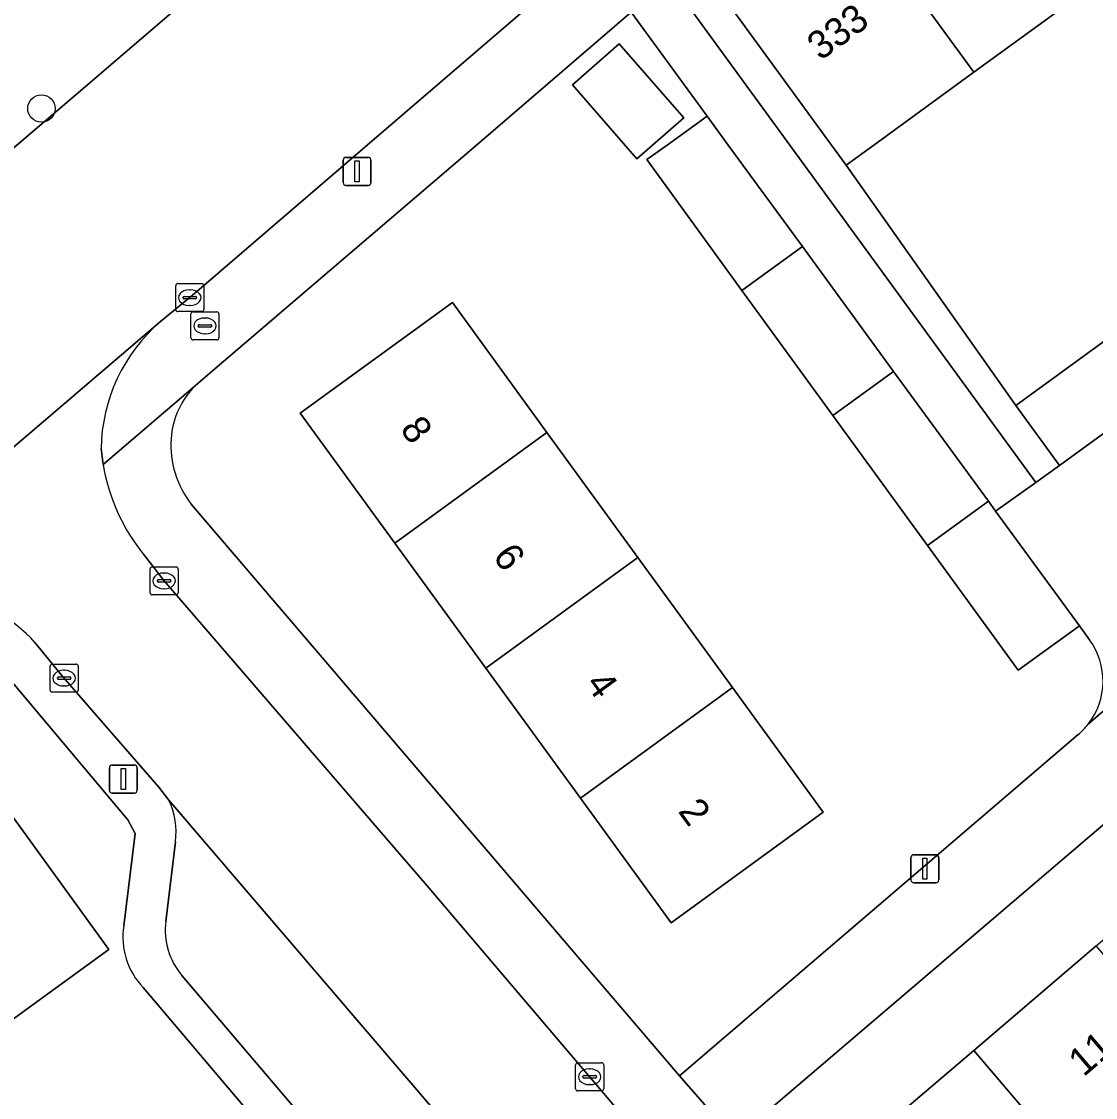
# Model space of a CAD drawing. Extents: x 159039 to 160102, y 381214 to 382524.
# Drawn here: x 159296.1 to 159334.39, y 381466.04 to 381504.4 of the extents above; entities that cross this region are included whole.
import ezdxf

# ---------------------------------------------------------------- set-up
doc = ezdxf.new("R2010")
doc.units = 0
for name, color, linetype in [('IMGEO_Boom', 7, 'Continuous'), ('IMGEO_Brandkraan', 7, 'Continuous'), ('IMGEO_Erf', 7, 'Continuous'), ('IMGEO_Groenvoorziening', 7, 'Continuous'), ('IMGEO_Kolk', 7, 'Continuous'), ('IMGEO_Lichtmast', 7, 'Continuous'), ('IMGEO_Pand', 7, 'Continuous'), ('IMGEO_Pand_nummerreeks', 7, 'Continuous'), ('IMGEO_Parkeervlak_open', 7, 'Continuous'), ('IMGEO_Rijbaan_lokaal_gesloten', 7, 'Continuous'), ('IMGEO_Rijbaan_lokaal_open', 7, 'Continuous'), ('IMGEO_Voetpad_open', 7, 'Continuous')]:
    doc.layers.add(name, color=color, linetype=linetype)

msp = doc.modelspace()

# ---------------------------------------------------------------- linework, layer by layer
at = {"layer": 'IMGEO_Boom'}
msp.add_circle((159296.812, 381501.302), 0.489, dxfattribs=at)
at = {"layer": 'IMGEO_Brandkraan'}
for p, q in [((159302.142, 381493.125), (159302.142, 381493.977)), ((159302.217, 381494.051), (159303.069, 381494.051)), ((159302.63, 381493.831), (159302.655, 381493.831)), ((159303.143, 381493.977), (159303.143, 381493.125)), ((159302.401, 381493.545), (159302.401, 381493.557)), ((159302.839, 381493.508), (159302.441, 381493.508)), ((159302.444, 381493.594), (159302.842, 381493.594)), ((159302.885, 381493.557), (159302.885, 381493.545)), ((159303.069, 381493.051), (159302.217, 381493.051)), ((159302.653, 381493.271), (159302.628, 381493.271))]:
    msp.add_line(p, q, dxfattribs=at)
for points in [[(159302.142, 381493.125), (159302.142, 381493.977)], [(159302.217, 381494.051), (159303.069, 381494.051)], [(159303.143, 381493.977), (159303.143, 381493.125)], [(159303.069, 381493.051), (159302.217, 381493.051)]]:
    msp.add_lwpolyline(points, dxfattribs=at)
for centre, radius, start, end in [((159302.219, 381493.975), 0.0765, 91.552, 178.448), ((159302.219, 381493.975), 0.0765, 91.552, 178.448), ((159303.067, 381493.975), 0.0765, 1.552, 88.448), ((159303.067, 381493.975), 0.0765, 1.552, 88.448), ((159302.441, 381493.554), 0.0403, 85.8775, 175.7526), ((159302.438, 381493.544), 0.0366, 178.938, 274.7102), ((159302.842, 381493.551), 0.043, 264.8664, 352.4533), ((159302.846, 381493.556), 0.0386, 1.7309, 96.639), ((159302.219, 381493.127), 0.0765, 181.552, 268.448), ((159302.219, 381493.127), 0.0765, 181.552, 268.448), ((159303.067, 381493.127), 0.0765, 271.552, 358.448), ((159303.067, 381493.127), 0.0765, 271.552, 358.448)]:
    msp.add_arc(centre, radius, start, end, dxfattribs=at)
for centre, major_axis, ratio, start_param, end_param in [((159302.629, 381493.551), (-0.387, 0.002), 0.722429, 4.712389, 7.853982), ((159302.654, 381493.551), (-0.39, 0.002), 0.717154, 1.570796, 4.712389)]:
    msp.add_ellipse(centre, major_axis=major_axis, ratio=ratio, start_param=start_param, end_param=end_param, dxfattribs=at)
at = {"layer": 'IMGEO_Erf'}
for points in [[(159334.646, 381505.941), (159330.052, 381502.597), (159326.485, 381500), (159325.501, 381499.284), (159331.551, 381490.716), (159334.784, 381493.064), (159336.342, 381490.923), (159337.788, 381491.975), (159339.116, 381492.941), (159337.559, 381495.079), (159340.829, 381497.453), (159344.336, 381500), (159345.362, 381500.745), (159349.862, 381504.013), (159353.089, 381506.357)], [(159325.031, 381490.357), (159321.789, 381494.812), (159318.393, 381499.48), (159319.118, 381500), (159320.55, 381501.028), (159317.844, 381504.732), (159312.319, 381500), (159302.583, 381491.662), (159302.308, 381491.427)], [(159334.18, 381482.359), (159333.817, 381482.856), (159331.64, 381481.272), (159328.405, 381485.718), (159325.031, 381490.357)], [(159302.152, 381487.194), (159319.563, 381466.81), (159333.778, 381478.977)], [(159299.748, 381472.159), (159300.152, 381475.447), (159299.893, 381475.941), (159295.018, 381481.729)], [(159295.252, 381476.781), (159299.214, 381471.315), (159294.541, 381467.929)], [(159294.53, 381454.94), (159296.091, 381452.788), (159297.79, 381454.02), (159298.801, 381454.752), (159297.24, 381456.904), (159300.71, 381459.419), (159305.261, 381462.717), (159306.821, 381460.565), (159307.749, 381461.325), (159300.446, 381469.957)]]:
    msp.add_lwpolyline(points, dxfattribs=at)
for points in [[(159318.045, 381499.513), (159315.742, 381502.147), (159317.415, 381503.609), (159319.718, 381500.975)], [(159318.076, 381485.295), (159321.45, 381480.657), (159324.688, 381476.207), (159319.264, 381472.261), (159316.027, 381476.711), (159312.653, 381481.348), (159309.41, 381485.806), (159306.042, 381490.435), (159311.466, 381494.381), (159314.834, 381489.752)], [(159353.568, 381466.332), (159356.93, 381469.203), (159358.656, 381467.182), (159359.612, 381467.998), (159357.886, 381470.019), (159362.143, 381473.653), (159366.296, 381477.198), (159368.022, 381475.177), (159369.913, 381476.791), (159364.087, 381483.617), (159355.565, 381493.598), (159321.537, 381464.546), (159335.677, 381447.899), (159337.911, 381449.806), (159336.35, 381451.634), (159340.649, 381455.304), (159344.05, 381458.207), (159345.776, 381456.186), (159346.746, 381457.014), (159345.02, 381459.035), (159349.355, 381462.736), (159351.081, 381460.715), (159352.008, 381461.507), (159350.282, 381463.528)], [(159347.282, 381473.694), (159343.069, 381470.098), (159338.734, 381466.397), (159334.362, 381462.665), (159330.206, 381459.117), (159325.893, 381464.168), (159330.049, 381467.715), (159334.421, 381471.448), (159338.756, 381475.149), (159342.969, 381478.745), (159347.286, 381482.43), (159351.543, 381486.064), (159355.841, 381489.733), (159360.153, 381484.682), (159355.856, 381481.014), (159351.599, 381477.38)]]:
    msp.add_lwpolyline(points, close=True, dxfattribs=at)
for centre, radius, start, end in [((159304.324, 381489.355), 2.891, 134.2059, 176.5428), ((159304.84, 381489.293), 3.411, 176.0271, 217.9783), ((159332.16, 381480.884), 2.501, 322.1067, 36.1428), ((159332.232, 381480.817), 2.403, 310.04, 322.324), ((159302.279, 381471.75), 2.564, 170.8183, 224.3573)]:
    msp.add_arc(centre, radius, start, end, dxfattribs=at)
at = {"layer": 'IMGEO_Groenvoorziening'}
msp.add_lwpolyline([(159325.501, 381499.284), (159324.981, 381500), (159321.492, 381504.791), (159320.117, 381506.679), (159319.202, 381505.896), (159332.26, 381487.965), (159333.111, 381488.573), (159331.551, 381490.716)], close=True, dxfattribs=at)
at = {"layer": 'IMGEO_Kolk'}
for p, q in [((159301.601, 381494.133), (159301.601, 381494.985)), ((159301.676, 381495.059), (159302.528, 381495.059)), ((159302.602, 381494.985), (159302.602, 381494.133)), ((159301.86, 381494.553), (159301.86, 381494.565)), ((159302.298, 381494.516), (159301.9, 381494.516)), ((159301.903, 381494.602), (159302.301, 381494.602)), ((159302.089, 381494.839), (159302.114, 381494.839)), ((159302.344, 381494.565), (159302.344, 381494.553)), ((159302.112, 381494.279), (159302.087, 381494.279)), ((159302.528, 381494.059), (159301.676, 381494.059)), ((159300.686, 381484.033), (159300.686, 381484.885)), ((159300.761, 381484.959), (159301.613, 381484.959)), ((159301.687, 381484.885), (159301.687, 381484.033)), ((159300.988, 381484.502), (159301.386, 381484.502)), ((159301.174, 381484.739), (159301.199, 381484.739)), ((159300.945, 381484.453), (159300.945, 381484.465)), ((159301.383, 381484.416), (159300.985, 381484.416)), ((159301.197, 381484.179), (159301.172, 381484.179)), ((159301.429, 381484.465), (159301.429, 381484.453)), ((159301.613, 381483.959), (159300.761, 381483.959)), ((159297.197, 381481.49), (159298.049, 381481.49)), ((159297.122, 381480.564), (159297.122, 381481.416)), ((159297.61, 381481.27), (159297.635, 381481.27)), ((159298.123, 381481.416), (159298.123, 381480.564)), ((159297.381, 381480.984), (159297.381, 381480.996)), ((159297.819, 381480.947), (159297.421, 381480.947)), ((159297.424, 381481.033), (159297.822, 381481.033)), ((159297.633, 381480.71), (159297.608, 381480.71)), ((159297.865, 381480.996), (159297.865, 381480.984)), ((159298.049, 381480.49), (159297.197, 381480.49)), ((159315.933, 381467.274), (159316.785, 381467.274)), ((159315.858, 381466.348), (159315.858, 381467.2)), ((159316.346, 381467.054), (159316.371, 381467.054)), ((159316.859, 381467.2), (159316.859, 381466.348)), ((159316.117, 381466.768), (159316.117, 381466.78)), ((159316.555, 381466.731), (159316.157, 381466.731)), ((159316.16, 381466.817), (159316.558, 381466.817)), ((159316.369, 381466.494), (159316.344, 381466.494)), ((159316.601, 381466.78), (159316.601, 381466.768)), ((159316.785, 381466.274), (159315.933, 381466.274))]:
    msp.add_line(p, q, dxfattribs=at)
for points in [[(159301.601, 381494.133), (159301.601, 381494.985)], [(159301.676, 381495.059), (159302.528, 381495.059)], [(159302.602, 381494.985), (159302.602, 381494.133)], [(159302.528, 381494.059), (159301.676, 381494.059)], [(159300.686, 381484.033), (159300.686, 381484.885)], [(159300.761, 381484.959), (159301.613, 381484.959)], [(159301.687, 381484.885), (159301.687, 381484.033)], [(159301.613, 381483.959), (159300.761, 381483.959)], [(159297.197, 381481.49), (159298.049, 381481.49)], [(159297.122, 381480.564), (159297.122, 381481.416)], [(159298.123, 381481.416), (159298.123, 381480.564)], [(159298.049, 381480.49), (159297.197, 381480.49)], [(159315.933, 381467.274), (159316.785, 381467.274)], [(159315.858, 381466.348), (159315.858, 381467.2)], [(159316.859, 381467.2), (159316.859, 381466.348)], [(159316.785, 381466.274), (159315.933, 381466.274)]]:
    msp.add_lwpolyline(points, dxfattribs=at)
for centre, radius, start, end in [((159301.678, 381494.983), 0.0765, 91.552, 178.448), ((159301.678, 381494.983), 0.0765, 91.552, 178.448), ((159302.526, 381494.983), 0.0765, 1.552, 88.448), ((159302.526, 381494.983), 0.0765, 1.552, 88.448), ((159301.9, 381494.562), 0.0403, 85.8775, 175.7526), ((159301.897, 381494.552), 0.0366, 178.938, 274.7102), ((159302.301, 381494.559), 0.043, 264.8664, 352.4533), ((159302.305, 381494.564), 0.0386, 1.7309, 96.639), ((159301.678, 381494.135), 0.0765, 181.552, 268.448), ((159301.678, 381494.135), 0.0765, 181.552, 268.448), ((159302.526, 381494.135), 0.0765, 271.552, 358.448), ((159302.526, 381494.135), 0.0765, 271.552, 358.448), ((159300.763, 381484.883), 0.0765, 91.552, 178.448), ((159300.763, 381484.883), 0.0765, 91.552, 178.448), ((159301.611, 381484.883), 0.0765, 1.552, 88.448), ((159301.611, 381484.883), 0.0765, 1.552, 88.448), ((159300.985, 381484.462), 0.0403, 85.8775, 175.7526), ((159301.39, 381484.464), 0.0386, 1.7309, 96.639), ((159300.982, 381484.452), 0.0366, 178.938, 274.7102), ((159301.386, 381484.459), 0.043, 264.8664, 352.4533), ((159300.763, 381484.035), 0.0765, 181.552, 268.448), ((159300.763, 381484.035), 0.0765, 181.552, 268.448), ((159301.611, 381484.035), 0.0765, 271.552, 358.448), ((159301.611, 381484.035), 0.0765, 271.552, 358.448), ((159297.199, 381481.414), 0.0765, 91.552, 178.448), ((159297.199, 381481.414), 0.0765, 91.552, 178.448), ((159298.047, 381481.414), 0.0765, 1.552, 88.448), ((159298.047, 381481.414), 0.0765, 1.552, 88.448), ((159297.421, 381480.993), 0.0403, 85.8775, 175.7526), ((159297.418, 381480.983), 0.0366, 178.938, 274.7102), ((159297.822, 381480.99), 0.043, 264.8664, 352.4533), ((159297.826, 381480.995), 0.0386, 1.7309, 96.639), ((159297.199, 381480.566), 0.0765, 181.552, 268.448), ((159297.199, 381480.566), 0.0765, 181.552, 268.448), ((159298.047, 381480.566), 0.0765, 271.552, 358.448), ((159298.047, 381480.566), 0.0765, 271.552, 358.448), ((159315.935, 381467.198), 0.0765, 91.552, 178.448), ((159315.935, 381467.198), 0.0765, 91.552, 178.448), ((159316.783, 381467.198), 0.0765, 1.552, 88.448), ((159316.783, 381467.198), 0.0765, 1.552, 88.448), ((159316.157, 381466.777), 0.0403, 85.8775, 175.7526), ((159316.154, 381466.767), 0.0366, 178.938, 274.7102), ((159316.558, 381466.774), 0.043, 264.8664, 352.4533), ((159316.562, 381466.779), 0.0386, 1.7309, 96.639), ((159315.935, 381466.35), 0.0765, 181.552, 268.448), ((159315.935, 381466.35), 0.0765, 181.552, 268.448), ((159316.783, 381466.35), 0.0765, 271.552, 358.448), ((159316.783, 381466.35), 0.0765, 271.552, 358.448)]:
    msp.add_arc(centre, radius, start, end, dxfattribs=at)
for centre, major_axis, ratio, start_param, end_param in [((159302.088, 381494.559), (-0.387, 0.002), 0.722429, 4.712389, 7.853982), ((159302.113, 381494.559), (-0.39, 0.002), 0.717154, 1.570796, 4.712389), ((159301.173, 381484.459), (-0.387, 0.002), 0.722429, 4.712389, 7.853982), ((159301.198, 381484.459), (-0.39, 0.002), 0.717154, 1.570796, 4.712389), ((159297.609, 381480.99), (-0.387, 0.002), 0.722429, 4.712389, 7.853982), ((159297.634, 381480.99), (-0.39, 0.002), 0.717154, 1.570796, 4.712389), ((159316.345, 381466.774), (-0.387, 0.002), 0.722429, 4.712389, 7.853982), ((159316.37, 381466.774), (-0.39, 0.002), 0.717154, 1.570796, 4.712389)]:
    msp.add_ellipse(centre, major_axis=major_axis, ratio=ratio, start_param=start_param, end_param=end_param, dxfattribs=at)
at = {"layer": 'IMGEO_Lichtmast'}
for p, q in [((159307.57, 381498.661), (159307.57, 381499.461)), ((159307.57, 381499.461), (159307.57, 381498.661)), ((159307.67, 381499.561), (159308.46, 381499.561)), ((159308.46, 381499.561), (159307.67, 381499.561)), ((159308.56, 381499.461), (159308.56, 381498.661)), ((159308.56, 381498.661), (159308.56, 381499.461)), ((159308.46, 381498.561), (159307.67, 381498.561)), ((159307.67, 381498.561), (159308.46, 381498.561)), ((159299.236, 381476.991), (159299.236, 381477.791)), ((159299.236, 381477.791), (159299.236, 381476.991)), ((159299.336, 381477.891), (159300.126, 381477.891)), ((159300.126, 381477.891), (159299.336, 381477.891)), ((159300.226, 381477.791), (159300.226, 381476.991)), ((159300.226, 381476.991), (159300.226, 381477.791)), ((159300.126, 381476.891), (159299.336, 381476.891)), ((159299.336, 381476.891), (159300.126, 381476.891)), ((159327.811, 381473.794), (159327.811, 381474.594)), ((159327.811, 381474.594), (159327.811, 381473.794)), ((159327.911, 381474.694), (159328.701, 381474.694)), ((159328.701, 381474.694), (159327.911, 381474.694)), ((159328.801, 381474.594), (159328.801, 381473.794)), ((159328.801, 381473.794), (159328.801, 381474.594)), ((159328.701, 381473.694), (159327.911, 381473.694)), ((159327.911, 381473.694), (159328.701, 381473.694))]:
    msp.add_line(p, q, dxfattribs=at)
for points in [[(159307.99, 381499.436), (159308.14, 381499.436), (159308.14, 381498.686), (159307.99, 381498.686), (159307.99, 381499.436)], [(159299.656, 381477.766), (159299.806, 381477.766), (159299.806, 381477.016), (159299.656, 381477.016), (159299.656, 381477.766)], [(159328.231, 381474.569), (159328.381, 381474.569), (159328.381, 381473.819), (159328.231, 381473.819), (159328.231, 381474.569)]]:
    msp.add_lwpolyline(points, dxfattribs=at)
for centre, start, end in [((159307.67, 381499.461), 90, 180), ((159307.67, 381499.461), 90, 180), ((159308.46, 381499.461), 0, 90), ((159308.46, 381499.461), 360, 90), ((159307.67, 381498.661), 180, 270), ((159307.67, 381498.661), 180, 270), ((159308.46, 381498.661), 270, 0), ((159308.46, 381498.661), 270, 0), ((159299.336, 381477.791), 90, 180), ((159299.336, 381477.791), 90, 180), ((159300.126, 381477.791), 0, 90), ((159300.126, 381477.791), 360, 90), ((159299.336, 381476.991), 180, 270), ((159299.336, 381476.991), 180, 270), ((159300.126, 381476.991), 270, 0), ((159300.126, 381476.991), 270, 0), ((159327.911, 381474.594), 90, 180), ((159327.911, 381474.594), 90, 180), ((159328.701, 381474.594), 0, 90), ((159328.701, 381474.594), 360, 90), ((159327.911, 381473.794), 180, 270), ((159327.911, 381473.794), 180, 270), ((159328.701, 381473.794), 270, 0), ((159328.701, 381473.794), 270, 0)]:
    msp.add_arc(centre, 0.1, start, end, dxfattribs=at)
at = {"layer": 'IMGEO_Pand'}
for points in [[(159330.633, 381511.45), (159326.041, 381508.104), (159330.052, 381502.597), (159334.646, 381505.941)], [(159326.041, 381508.104), (159321.492, 381504.791), (159324.981, 381500), (159325.501, 381499.284), (159326.485, 381500), (159330.052, 381502.597)], [(159318.045, 381499.513), (159319.718, 381500.975), (159317.415, 381503.609), (159315.742, 381502.147)], [(159323.944, 381496.38), (159321.301, 381500), (159320.55, 381501.028), (159319.118, 381500), (159318.393, 381499.48), (159321.789, 381494.812)], [(159323.944, 381496.38), (159321.789, 381494.812), (159325.031, 381490.357), (159327.192, 381491.93)], [(159309.41, 381485.806), (159314.834, 381489.752), (159311.466, 381494.381), (159306.042, 381490.435)], [(159334.784, 381493.064), (159331.551, 381490.716), (159333.111, 381488.573), (159336.342, 381490.923)], [(159330.575, 381487.297), (159327.192, 381491.93), (159325.031, 381490.357), (159328.405, 381485.718)], [(159309.41, 381485.806), (159312.653, 381481.348), (159318.076, 381485.295), (159314.834, 381489.752)], [(159330.575, 381487.297), (159328.405, 381485.718), (159331.64, 381481.272), (159333.817, 381482.856), (159330.831, 381486.946)], [(159312.653, 381481.348), (159316.027, 381476.711), (159321.45, 381480.657), (159318.076, 381485.295)], [(159321.45, 381480.657), (159316.027, 381476.711), (159319.264, 381472.261), (159324.688, 381476.207)], [(159290.579, 381473.395), (159294.541, 381467.929), (159299.214, 381471.315), (159295.252, 381476.781)], [(159334.421, 381471.448), (159330.049, 381467.715), (159334.362, 381462.665), (159338.734, 381466.397)], [(159330.049, 381467.715), (159325.893, 381464.168), (159330.206, 381459.117), (159334.362, 381462.665)]]:
    msp.add_lwpolyline(points, close=True, dxfattribs=at)
at = {"layer": 'IMGEO_Parkeervlak_open'}
for points in [[(159320.759, 381454.056), (159311.037, 381465.319), (159301.358, 381476.642)], [(159301.594, 381475.155), (159301.243, 381472.318)], [(159301.82, 381470.391), (159306.504, 381464.885), (159308.202, 381462.89), (159309.131, 381461.814), (159310.867, 381459.802), (159313.267, 381457.023), (159314.26, 381455.872)]]:
    msp.add_lwpolyline(points, dxfattribs=at)
for centre, radius, start, end in [((159298.87, 381475.485), 2.744, 353.0926, 24.9436), ((159303.734, 381472.014), 2.509, 173.0396, 220.2988)]:
    msp.add_arc(centre, radius, start, end, dxfattribs=at)
at = {"layer": 'IMGEO_Rijbaan_lokaal_gesloten'}
msp.add_lwpolyline([(159302.526, 381505.654), (159297.968, 381501.732), (159295.931, 381500), (159281.518, 381487.748), (159278.677, 381485.329), (159274.306, 381481.608), (159279.589, 381475.401), (159281.201, 381476.782), (159287.127, 381481.79), (159288.533, 381483.013), (159301.064, 381493.711), (159302.188, 381494.631), (159308.43, 381500), (159317.66, 381507.94), (159332.693, 381520.763), (159327.779, 381527.216), (159319.433, 381520.175), (159305.767, 381508.444)], close=True, dxfattribs=at)
at = {"layer": 'IMGEO_Rijbaan_lokaal_open'}
for points in [[(159368.891, 381509.056), (159365.178, 381505.9), (159358.272, 381500), (159353.947, 381496.32), (159353.172, 381495.652), (159339.895, 381484.327), (159337.979, 381482.69), (159334.134, 381479.348)], [(159301.064, 381493.711), (159288.533, 381483.013)], [(159333.778, 381478.977), (159319.563, 381466.81), (159321.537, 381464.546), (159355.565, 381493.598)], [(159299.011, 381488.603), (159298.939, 381489.175)], [(159319.829, 381462.724), (159317.462, 381465.475), (159310.569, 381473.58), (159301.184, 381484.461), (159300.454, 381485.405)], [(159296.583, 381482.266), (159297.593, 381481.027), (159301.004, 381477.098), (159301.358, 381476.642), (159311.037, 381465.319), (159320.759, 381454.056), (159329.812, 381443.465), (159333.778, 381438.529), (159340.657, 381430.507), (159341.136, 381429.955), (159344.946, 381433.224), (159344.557, 381433.676), (159341.053, 381437.737), (159337.243, 381442.153), (159335.969, 381443.63), (159334.37, 381445.546), (159331.922, 381448.478), (159326.533, 381454.933), (159319.829, 381462.724)]]:
    msp.add_lwpolyline(points, dxfattribs=at)
for centre, radius, start, end in [((159305.058, 381489.074), 6.12, 130.741, 179.0552), ((159305.848, 381489.763), 6.935, 189.633, 218.9387), ((159292.249, 381478.261), 5.901, 42.7437, 76.8886), ((159332.232, 381480.817), 2.403, 310.04, 322.324)]:
    msp.add_arc(centre, radius, start, end, dxfattribs=at)
at = {"layer": 'IMGEO_Voetpad_open'}
for points in [[(159403.253, 381581.19), (159401.441, 381579.651), (159391.641, 381571.315), (159381.263, 381562.391), (159379.14, 381560.565), (159377.401, 381559.069), (159375.25, 381557.212), (159372.533, 381554.867), (159361.516, 381545.448), (159356.286, 381541.009), (159356.146, 381540.888), (159351.483, 381536.862), (159349.151, 381534.849), (159346.704, 381532.736), (159334.842, 381522.599), (159332.693, 381520.763), (159317.66, 381507.94), (159308.43, 381500), (159302.188, 381494.631), (159301.064, 381493.711)], [(159298.939, 381489.175), (159299.011, 381488.603), (159302.305, 381491.425), (159302.308, 381491.427), (159302.583, 381491.662), (159312.319, 381500), (159317.844, 381504.732), (159319.202, 381505.896), (159320.117, 381506.679), (159350.383, 381532.6)], [(159232.898, 381449.89), (159232.488, 381448.686), (159230.747, 381444.157), (159230.307, 381443.034), (159232.903, 381442.592), (159233.403, 381442.507), (159235.381, 381448.161), (159241.329, 381453.344), (159243.638, 381455.319), (159245.889, 381457.245), (159250.208, 381460.939), (159269.659, 381477.653), (159272.211, 381479.825), (159274.306, 381481.608), (159278.677, 381485.329), (159281.518, 381487.748), (159295.931, 381500), (159297.968, 381501.732), (159302.526, 381505.654), (159305.767, 381508.444), (159319.433, 381520.175)], [(159368.096, 381511.287), (159366.63, 381513.045), (159364.969, 381511.745), (159361.874, 381509.494), (159360.588, 381508.559), (159357.419, 381506.254), (159356.043, 381505.253), (159354.638, 381504.231), (159351.412, 381501.885), (159348.821, 381500), (159346.915, 381498.614), (159342.384, 381495.318), (159339.116, 381492.941), (159337.788, 381491.975), (159336.342, 381490.923), (159333.111, 381488.573), (159332.26, 381487.965), (159330.831, 381486.946), (159333.817, 381482.856), (159334.18, 381482.359)], [(159302.308, 381491.427), (159302.305, 381491.425), (159299.011, 381488.603)], [(159321.537, 381464.546), (159319.563, 381466.81), (159302.152, 381487.194)], [(159300.454, 381485.405), (159301.184, 381484.461), (159310.569, 381473.58), (159317.462, 381465.475), (159319.829, 381462.724), (159326.533, 381454.933), (159331.922, 381448.478), (159334.37, 381445.546), (159335.969, 381443.63)], [(159334.134, 381479.348), (159337.979, 381482.69)], [(159301.358, 381476.642), (159301.004, 381477.098), (159297.593, 381481.027), (159296.583, 381482.266)], [(159295.018, 381481.729), (159299.893, 381475.941), (159300.152, 381475.447), (159299.748, 381472.159)], [(159301.243, 381472.318), (159301.594, 381475.155)], [(159314.26, 381455.872), (159313.267, 381457.023), (159310.867, 381459.802), (159309.131, 381461.814), (159308.202, 381462.89), (159306.504, 381464.885), (159301.82, 381470.391)], [(159300.446, 381469.957), (159307.749, 381461.325), (159309.007, 381459.902), (159309.02, 381459.887), (159309.567, 381459.253), (159312.01, 381456.432), (159313.561, 381454.682)]]:
    msp.add_lwpolyline(points, dxfattribs=at)
msp.add_lwpolyline([(159319.202, 381505.896), (159317.844, 381504.732), (159320.55, 381501.028), (159321.301, 381500), (159323.944, 381496.38), (159327.192, 381491.93), (159330.575, 381487.297), (159330.831, 381486.946), (159332.26, 381487.965)], close=True, dxfattribs=at)
for centre, radius, start, end in [((159305.058, 381489.074), 6.12, 130.741, 179.0552), ((159304.324, 381489.355), 2.891, 134.2059, 176.5428), ((159304.84, 381489.293), 3.411, 176.0271, 217.9783), ((159305.848, 381489.763), 6.935, 189.633, 218.9387), ((159292.249, 381478.261), 5.901, 42.7437, 76.8886), ((159332.16, 381480.884), 2.501, 322.1067, 36.1428), ((159298.87, 381475.485), 2.744, 353.0926, 24.9436), ((159303.734, 381472.014), 2.509, 173.0396, 220.2988), ((159302.279, 381471.75), 2.564, 170.8183, 224.3573)]:
    msp.add_arc(centre, radius, start, end, dxfattribs=at)

# ---------------------------------------------------------------- texts
at = {"layer": 'IMGEO_Pand_nummerreeks'}
for s, rotation, p in [('333', 36.0709, (159324.586, 381502.986)), ('8', 306.0367, (159309.573, 381489.865)), ('6', 306.0367, (159312.876, 381485.325)), ('4', 306.0367, (159316.182, 381480.781)), ('2', 306.0367, (159319.486, 381476.24)), ('11', 40.4856, (159333.967, 381466.749))]:
    msp.add_text(s, height=1, rotation=rotation, dxfattribs=at).set_placement(p)

doc.saveas('drawing.dxf')
